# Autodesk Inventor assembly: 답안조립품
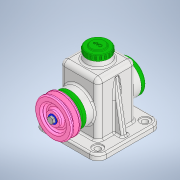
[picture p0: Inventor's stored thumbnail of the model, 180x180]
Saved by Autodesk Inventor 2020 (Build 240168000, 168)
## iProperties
Created: 2021-07
Part Number: 답안조립품
Document SubType Name: Assembly
Designer: Owner
Author: Owner
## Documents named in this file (14)
- C:\Users\Owner\Desktop\710715V1011\답안조립품.iam
- C:\Users\Owner\Desktop\710715V1011\본체.ipt
- C:\Users\Owner\Desktop\710715V1011\710715V1011\V-벨트풀리.ipt
- C:\Users\Owner\Desktop\710715V1011\710715V1011\뒤커버.ipt
- C:\Users\Owner\Desktop\710715V1011\710715V1011\멈춤링 15 x 1.ipt
- C:\Users\Owner\Desktop\710715V1011\710715V1011\베어링 15 x 35 x 11.ipt
- C:\Users\Owner\Desktop\710715V1011\710715V1011\볼트 M4 x 10.ipt
- C:\Users\Owner\Desktop\710715V1011\710715V1011\볼트 M6 x 12.ipt
- C:\Users\Owner\Desktop\710715V1011\710715V1011\상부캡.ipt
- C:\Users\Owner\Desktop\710715V1011\710715V1011\앞커버.ipt
- C:\Users\Owner\Desktop\710715V1011\710715V1011\오일실 15 25 7.ipt
- C:\Users\Owner\Desktop\710715V1011\710715V1011\와셔.ipt
- C:\Users\Owner\Desktop\710715V1011\710715V1011\축.ipt
- C:\Users\Owner\Desktop\710715V1011\710715V1011\키 5 x 5 x 14.ipt
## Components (1 placed, 1 different names)
1. V-벨트풀리:1 — 플러쉬:1
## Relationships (1: Flush 1)
- 플러쉬:1 [Flush]: V-벨트풀리:1
